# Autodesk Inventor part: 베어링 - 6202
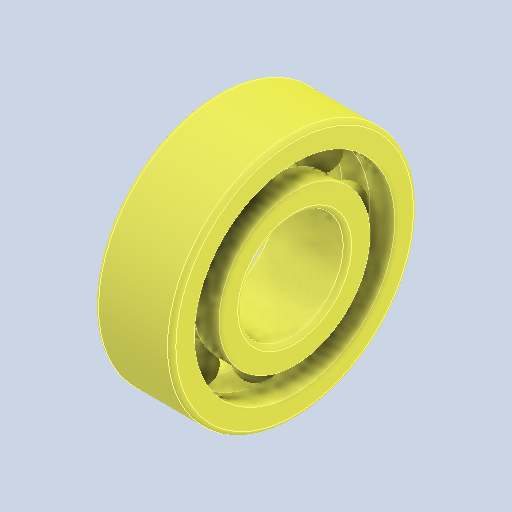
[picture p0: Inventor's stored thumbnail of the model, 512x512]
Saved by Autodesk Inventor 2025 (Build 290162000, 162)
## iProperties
Created: 2024-07
Part Number: 베어링 - 6202
Material: 강, 연강
Description: 깊은 그루브 볼 베어링
Document SubType Name: Modeling
Designer: Administrator
Density: 7.86 g/cm^3
Appearance: 기본값
Author: jhkim
Sending System: Autodesk Inventor 2025
Preprocessor: ST-DEVELOPER v20
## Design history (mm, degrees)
feature "Solid1"
feature "Solid1:1"
feature "Solid1:2"
feature "Solid1:3"
feature "Solid1:4"
feature "Solid1:5"
feature "Solid1:6"
feature "Solid1:7"
feature "Solid1:8"
feature "Solid1:9"
node "솔리드1"
node "솔리드2"
node "솔리드3"
node "솔리드4"
node "솔리드5"
node "솔리드6"
node "솔리드7"
node "솔리드8"
node "솔리드9"
node "솔리드10"
